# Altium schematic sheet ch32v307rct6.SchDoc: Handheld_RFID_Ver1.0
size A2; Date: 20160517; DocumentNumber: 1/1; Revision: Ver1.0
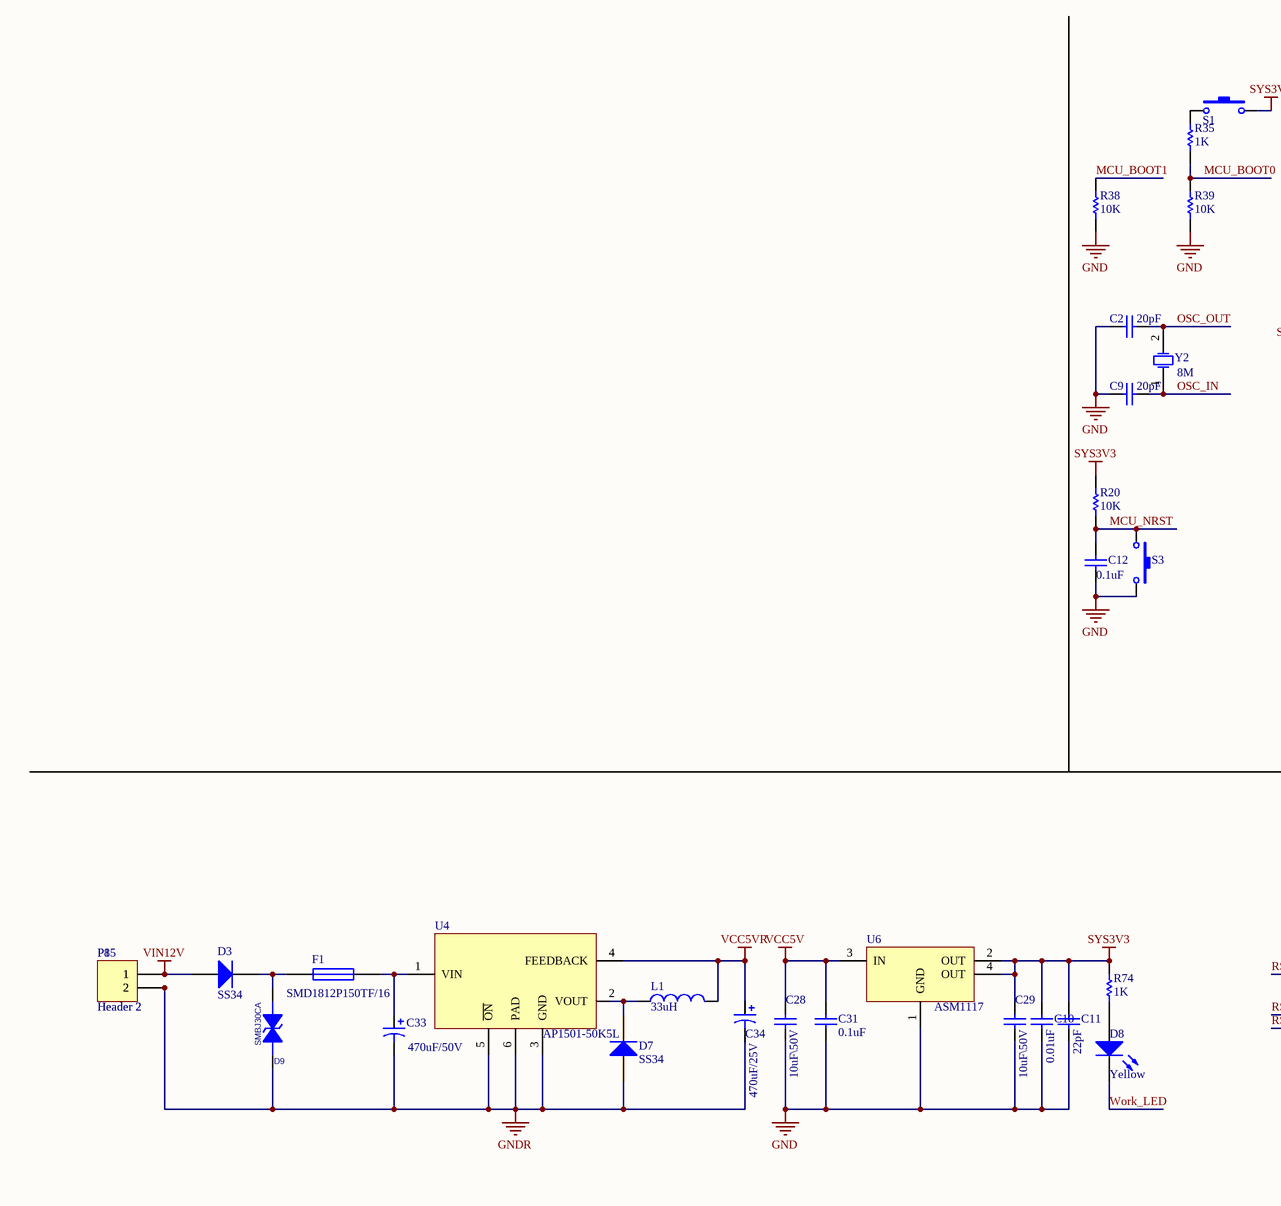
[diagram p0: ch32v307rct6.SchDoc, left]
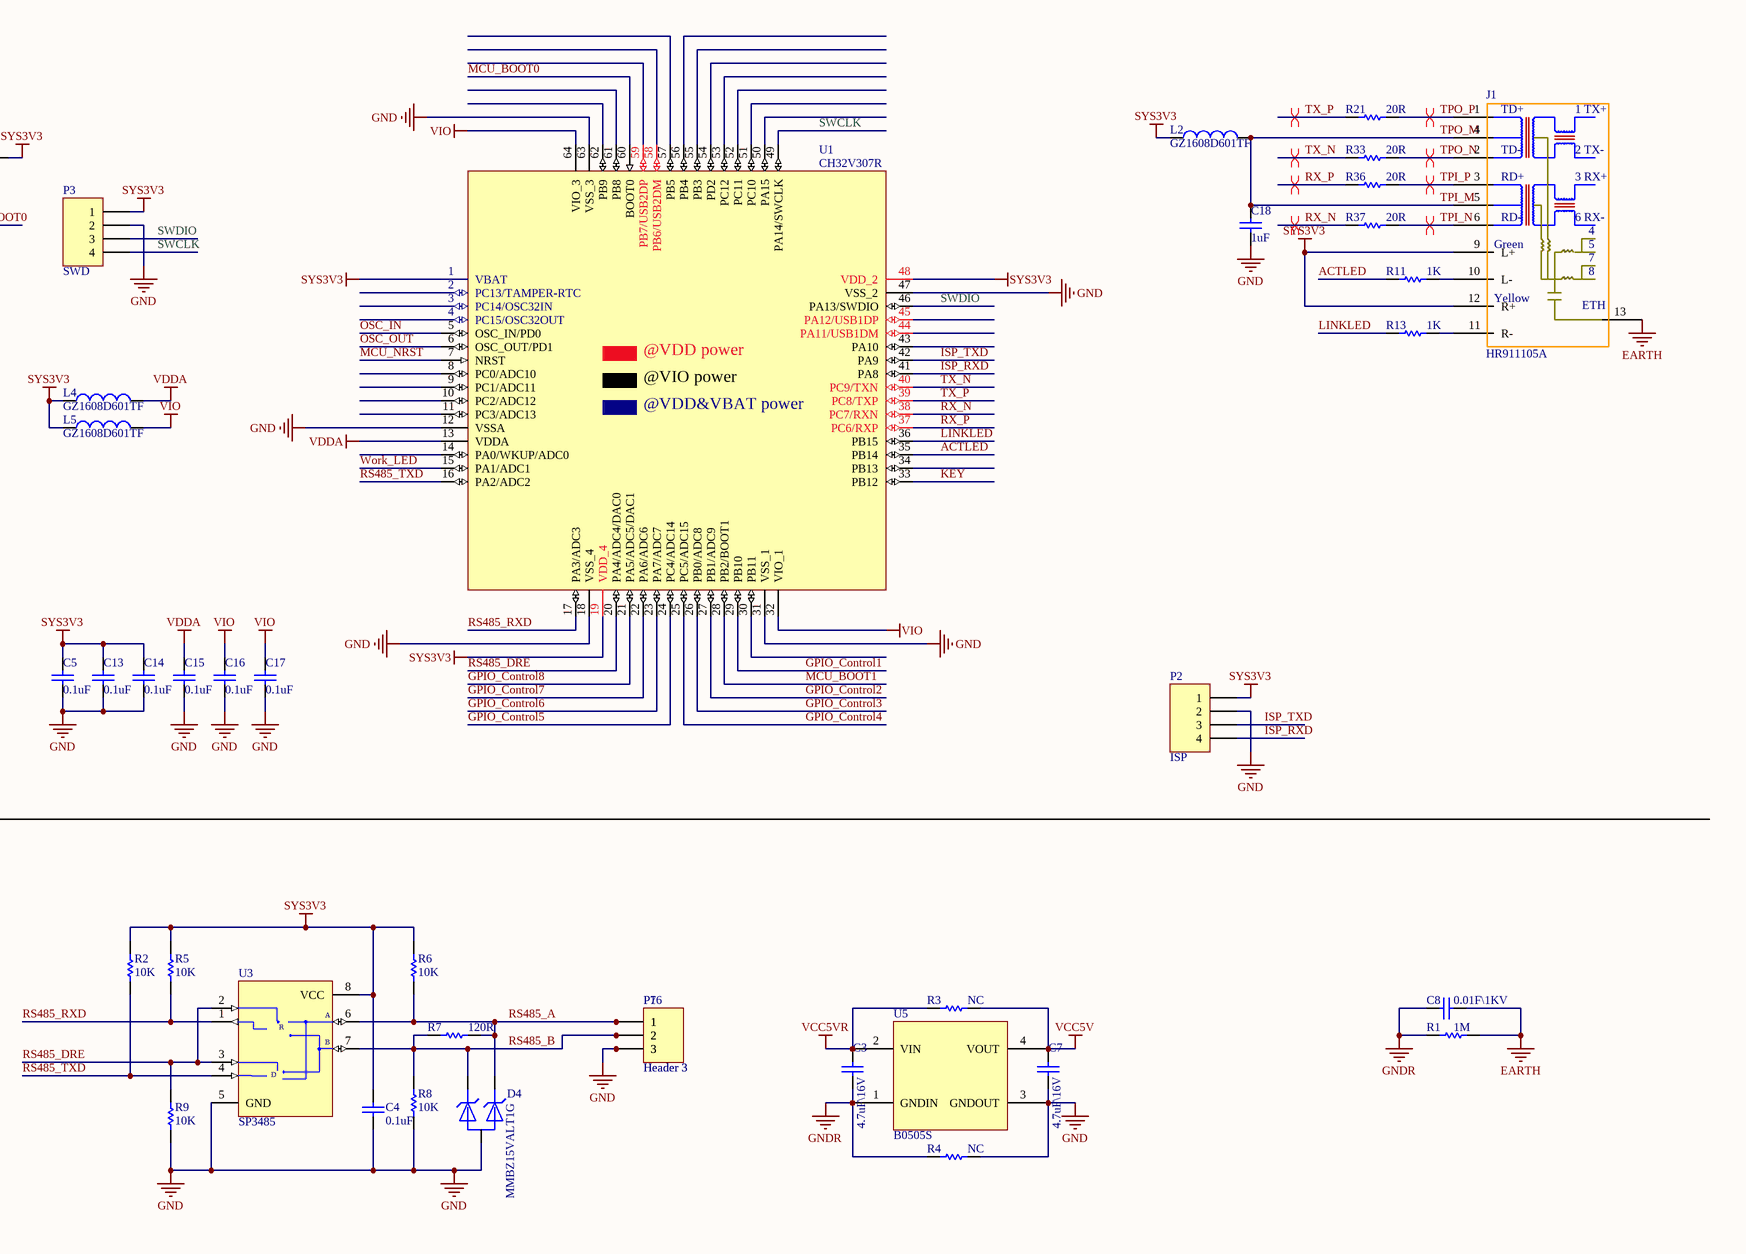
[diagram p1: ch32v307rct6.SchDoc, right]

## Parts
C2  value 20pF  [0603ca]  (hidden comment: Cap Semi)
C3  value 4.7uF\16V  [1206_C]  (hidden comment: Cap Semi)
C4  value 0.1uF  [0603ca]  (hidden comment: Cap Semi)
C5  value 0.1uF  [0603ca]  (hidden comment: Cap Semi)
C7  value 4.7uF\16V  [1206_C]  (hidden comment: Cap Semi)
C8  value 0.01F\1KV  [1206_C]  (hidden comment: Cap Semi)
C9  value 20pF  [0603ca]  (hidden comment: Cap Semi)
C10  value 0.01uF  [0603ca]  (hidden comment: Cap Semi)
C11  value 22pF  [0603ca]  (hidden comment: Cap Semi)
C12  value 0.1uF  [0603ca]  (hidden comment: Cap Semi)
C13  value 0.1uF  [0603ca]  (hidden comment: Cap Semi)
C14  value 0.1uF  [0603ca]  (hidden comment: Cap Semi)
C15  value 0.1uF  [0603ca]  (hidden comment: Cap Semi)
C16  value 0.1uF  [0603ca]  (hidden comment: Cap Semi)
C17  value 0.1uF  [0603ca]  (hidden comment: Cap Semi)
C18  value 1uF  [0603ca]  (hidden comment: Cap Semi)
C28  value 10uF\50V  [1206_C]  (hidden comment: Cap Semi)
C29  value 10uF\50V  [1206_C]  (hidden comment: Cap Semi)
C31  value 0.1uF  [0603ca]  (hidden comment: Cap Semi)
C33  value 470uF/50V  [CAP-SMD_BD10.0-L10.3-W10.3-FD]  (hidden comment: Cap Pol1)
C34  value 470uF/25V  [CAP-SMD_BD6.3-L6.6-W6.6-FD]  (hidden comment: Cap Pol1)
D3  SS34  [LC-SMA(DO-214AC)_S5]
D4  MMBZ15VALT1G  [SOT-23]
D7  SS34  [LC-SMA(DO-214AC)_S5]
D8  Yellow  [LED_0603]
D9  SMBJ30CA  [SOD-214AA]
F1  value SMD1812P150TF/16  [F1812]  (hidden comment: FUSE)
J1  HR911105A  [HR911105A]
L1  33uH  [IND-SMD_L6.0-W6.0]
L2  value GZ1608D601TF  [0603LA]  (hidden comment: Inductor)
L4  value GZ1608D601TF  [0603LA]  (hidden comment: Inductor)
L5  value GZ1608D601TF  [0603LA]  (hidden comment: Inductor)
P2  ISP  [HDR1X4]
P3  SWD  [HDR1X4]
P7  Header 3  [WJ2EDGR-5.08-3P]
P8  Header 2  [WJ2EDGR-5.08-2P]
P15  Header 2  [WJ500V-5.08-2P]
P16  Header 3  [WJ500V-5.08-3P]
R1  value 1M  [1206_R]  (hidden comment: Res)
R2  value 10K  [0603ra]  (hidden comment: Res)
R3  value NC  [0603ra]  (hidden comment: Res)
R4  value NC  [0603ra]  (hidden comment: Res)
R5  value 10K  [0603ra]  (hidden comment: Res)
R6  value 10K  [0603ra]  (hidden comment: Res)
R7  value 120R  [0603ra]  (hidden comment: Res)
R8  value 10K  [0603ra]  (hidden comment: Res)
R9  value 10K  [0603ra]  (hidden comment: Res)
R11  value 1K  [0603ra]  (hidden comment: Res)
R13  value 1K  [0603ra]  (hidden comment: Res)
R20  value 10K  [0603ra]  (hidden comment: Res)
R21  value 20R  [0603ra]  (hidden comment: Res)
R33  value 20R  [0603ra]  (hidden comment: Res)
R35  value 1K  [0603ra]  (hidden comment: Res)
R36  value 20R  [0603ra]  (hidden comment: Res)
R37  value 20R  [0603ra]  (hidden comment: Res)
R38  value 10K  [0603ra]  (hidden comment: Res)
R39  value 10K  [0603ra]  (hidden comment: Res)
R74  value 1K  [0603ra]  (hidden comment: Res)
S1  SW-PB  [SW-SMD_L3.9-W3.0-P4.45]  (value not drawn)
S3  SW-PB  [SW-SMD_L3.9-W3.0-P4.45]  (value not drawn)
U1  CH32V307R  [LQFP64M_10x10]
U3  SP3485  [SOIC-8L]
U4  AP1501-50K5L  [TO-263-6N]
U5  B0505S  [B0505S_1W]
U6  ASM1117  [SOT223-4M]
Y2  8M  [OSC]

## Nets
EARTH: C8.1 J1.13 R1.1
GND: C2.2 C4.1 C5.2 C7.1 C9.2 C10.1 C11.1 C12.2 C13.2 C14.2 C15.2 C16.2 C17.2 C18.2 C28.1 C29.1 C31.1 D4.3(A) P2.2 P3.2 P7.3 P16.3 R4.2 R8.1 R9.1 R38.2 R39.2 S3.2 U1.12(VSSA) U1.18(VSS_4) U1.31(VSS_1) U1.47(VSS_2) U1.63(VSS_3) U3.5(GND) U5.3(GNDOUT) U6.1(GND)
GNDR: C3.1 C8.2 C33.2 C34.2 D7.1(A) D9.2 P8.2 P15.2 R1.2 R4.1 U4.3(GND) U4.5(~{ON}) U4.6(PAD) U5.1(GNDIN)
SYS3V3: C4.2 C5.1 C10.2 C11.2 C13.1 C14.1 C29.2 J1.9(L+) J1.12(R+) L2.1 L4.1 L5.1 P2.1 P3.1 R2.2 R5.2 R6.2 R20.1 R74.1 S1.2 U1.1(VBAT) U1.19(VDD_4) U1.48(VDD_2) U3.8(VCC) U6.2(OUT) U6.4(OUT)
VCC5V: C7.2 C28.2 C31.2 R3.2 U5.4(VOUT) U6.3(IN)
VCC5VR: C3.2 C34.1 L1.2 R3.1 U4.4(FEEDBACK) U5.2(VIN)
VDDA: C15.1 L4.2 U1.13(VDDA)
VIN12V: D3.1(A) P8.1 P15.1
VIO: C16.1 C17.1 L5.2 U1.32(VIO_1) U1.64(VIO_3)
ACTLED: R11.2 U1.35(PB14)
GPIO_Control1: U1.29(PB10)
GPIO_Control2: U1.27(PB1/ADC9)
GPIO_Control3: U1.26(PB0/ADC8)
GPIO_Control4: U1.25(PC5/ADC15)
GPIO_Control5: U1.24(PC4/ADC14)
GPIO_Control6: U1.23(PA7/ADC7)
GPIO_Control7: U1.22(PA6/ADC6)
GPIO_Control8: U1.21(PA5/ADC5/DAC1)
ISP_RXD: P2.4 U1.41(PA8)
ISP_TXD: P2.3 U1.42(PA9)
KEY: U1.33(PB12)
LINKLED: R13.2 U1.36(PB15)
MCU_BOOT0: R35.2 R39.1 U1.60(BOOT0)
MCU_BOOT1: R38.1 U1.28(PB2/BOOT1)
MCU_NRST: C12.1 R20.2 S3.1 U1.7(NRST)
OSC_IN: C9.1 U1.5(OSC_IN/PD0) Y2.1(OSC1)
OSC_OUT: C2.1 U1.6(OSC_OUT/PD1) Y2.2(OSC2)
RS485_A: D4.1(C1) P7.1 P16.1 R6.1 R7.1 U3.6(A)
RS485_B: D4.2(C2) P7.2 P16.2 R7.2 R8.2 U3.7(B)
RS485_DRE: R9.2 U1.20(PA4/ADC4/DAC0) U3.2(~{RE}) U3.3(DE)
RS485_RXD: R5.1 U1.17(PA3/ADC3) U3.1(RO)
RS485_TXD: R2.1 U1.16(PA2/ADC2) U3.4(DI)
RX_N: R37.2 U1.38(PC7/RXN)
RX_P: R36.2 U1.37(PC6/RXP)
SWCLK: P3.4 U1.49(PA14/SWCLK)
SWDIO: P3.3 U1.46(PA13/SWDIO)
TPI_M: C18.1 J1.4 J1.5 L2.2  [also labelled TPO_M]
TPI_N: J1.6 R37.1
TPI_P: J1.3 R36.1
TPO_N: J1.2 R33.1
TPO_P: J1.1 R21.1
TX_N: R33.2 U1.40(PC9/TXN)
TX_P: R21.2 U1.39(PC8/TXP)
Work_LED: D8.2(K) U1.15(PA1/ADC1)
NetC33_1: C33.1 F1.1 U4.1(VIN)
NetD3_2: D3.2(K) D9.1 F1.2
NetD7_2: D7.2(K) L1.1 U4.2(VOUT)
NetD8_1: D8.1(A) R74.2
NetJ1_10: J1.10(L-) R11.1
NetJ1_11: J1.11(R-) R13.1
NetR35_1: R35.1 S1.1

Not connected (* = marked no-connect by the designer): U1 2(PC13/TAMPER-RTC) 3(PC14/OSC32IN) 4(PC15/OSC32OUT) 8(PC0/ADC10) 9(PC1/ADC11) 10(PC2/ADC12) 11(PC3/ADC13) 14(PA0/WKUP/ADC0) 30(PB11) 34(PB13) 43(PA10) 44(PA11/USB1DM) 45(PA12/USB1DP) 50(PA15) 51(PC10) 52(PC11) 53(PC12) 54(PD2) 55(PB3) 56(PB4) 57(PB5) 58(PB6/USB2DM) 59(PB7/USB2DP) 61(PB8) 62(PB9)

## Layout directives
differential pair: RX_N, RX_P, TPI_N, TPI_P, TPO_N, TPO_P, TX_N, TX_P

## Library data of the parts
C2-C5 C7-C18 C28 C29 C31 = Cap Semi: Capacitor (Semiconductor SIM Model)
C33 C34 = Cap Pol1: Polarized Capacitor (Radial)
D3 D7 = Diode: Default Diode
D4 = GSOT05C-GS08: PARTS: 1; OriginalSymbolOrigin: (20,40); CODE: 15040152; PKG_TYPE: SOT23; LEVEL: STD; DEVICE: GSOT05C_GS08
D8 = LED2: Typical RED, GREEN, YELLOW, AMBER GaAs LED
D9 = DIODE BI-DIR TRIG
F1 = Fuse 1
L1 L2 L4 L5 = Inductor: Code_IEC: 1005
P2 P3 = Header 4: Header, 4-Pin
P7 P16 = Header 3: Header, 3-Pin
P8 P15 = Header 2: Header, 2-Pin
R1-R9 R11 R13 R20 R21 R33 R35-R39 R74 = Res1: Resistor
S1 S3 = SW-PB: Switch
U1 = CH32V307R: RISC-V FPU HD-MCU, 144MHz, USB_480M, USB OTG, 1000M Ethernet MAC, 2*CAN
U3 = MAX485ESA: Low-Power, Slew-Rate-Limited RS-485/RS-422 Transceiver
U4 = LM2575S-5
U5 = B1212S
Y2 = XTAL: Crystal Oscillator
